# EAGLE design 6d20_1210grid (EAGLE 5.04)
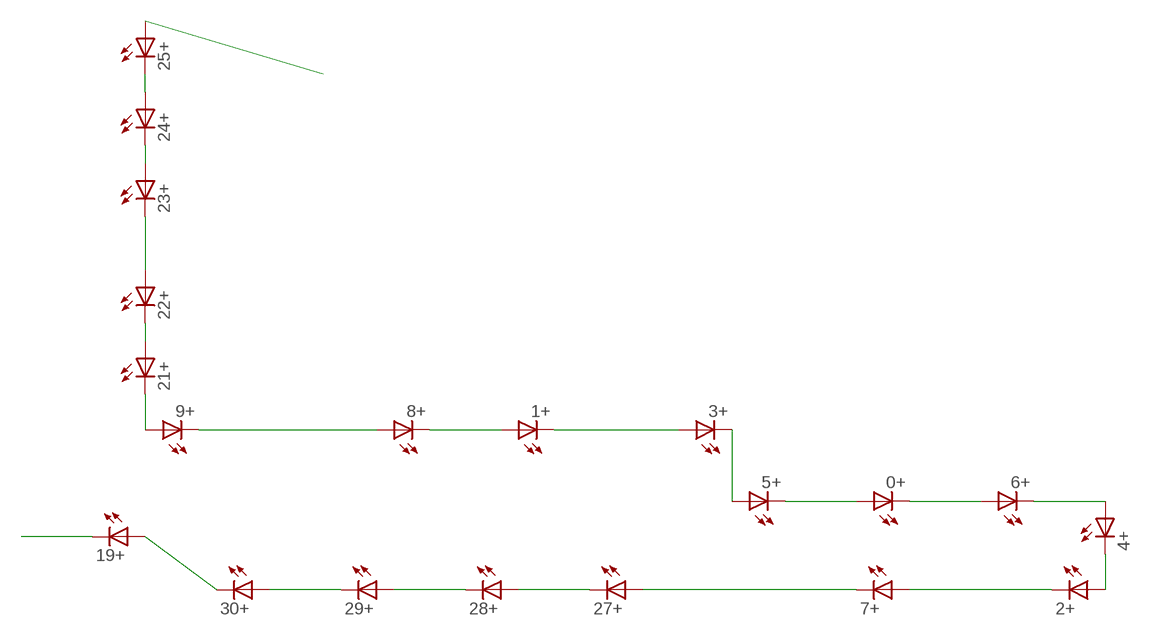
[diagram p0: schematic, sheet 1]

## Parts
0+  LED1210  [1210]
1+  LED1210  [1210]
2+  LED1210  [1210]
3+  LED1210  [1210]
4+  LED1210  [1210]
5+  LED1210  [1210]
6+  LED1210  [1210]
7+  LED1210  [1210]
8+  LED1210  [1210]
9+  LED1210  [1210]
19+  LED1210  [1210]
21+  LED1210  [1210]
22+  LED1210  [1210]
23+  LED1210  [1210]
24+  LED1210  [1210]
25+  LED1210  [1210]
27+  LED1210  [1210]
28+  LED1210  [1210]
29+  LED1210  [1210]
30+  LED1210  [1210]

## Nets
MINUS: 19+.P$2(C)
N$4: 19+.P$1(A) 30+.P$2(C)
N$6: 8+.P$1(A) 9+.P$2(C)
N$7: 29+.P$2(C) 30+.P$1(A)
N$8: 28+.P$2(C) 29+.P$1(A)
N$9: 27+.P$2(C) 28+.P$1(A)
N$12: 2+.P$2(C) 7+.P$1(A)
N$13: 7+.P$2(C) 27+.P$1(A)
N$14: 2+.P$1(A) 4+.P$2(C)
N$15: 4+.P$1(A) 6+.P$2(C)
N$16: 0+.P$2(C) 6+.P$1(A)
N$17: 0+.P$1(A) 5+.P$2(C)
N$18: 3+.P$2(C) 5+.P$1(A)
N$19: 1+.P$2(C) 3+.P$1(A)
N$20: 1+.P$1(A) 8+.P$2(C)
N$23: 9+.P$1(A) 21+.P$2(C)
N$24: 21+.P$1(A) 22+.P$2(C)
N$25: 22+.P$1(A) 23+.P$2(C)
N$26: 24+.P$1(A) 25+.P$2(C)
N$28: 23+.P$1(A) 24+.P$2(C)
PLUS: 25+.P$1(A)

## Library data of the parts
0+ 1+ 2+ 3+ 4+ 5+ 6+ 7+ 8+ 9+ 19+ 21+ 22+ 23+ 24+ 25+ 27+ 28+ 29+ 30+ = led(2):LED: LED

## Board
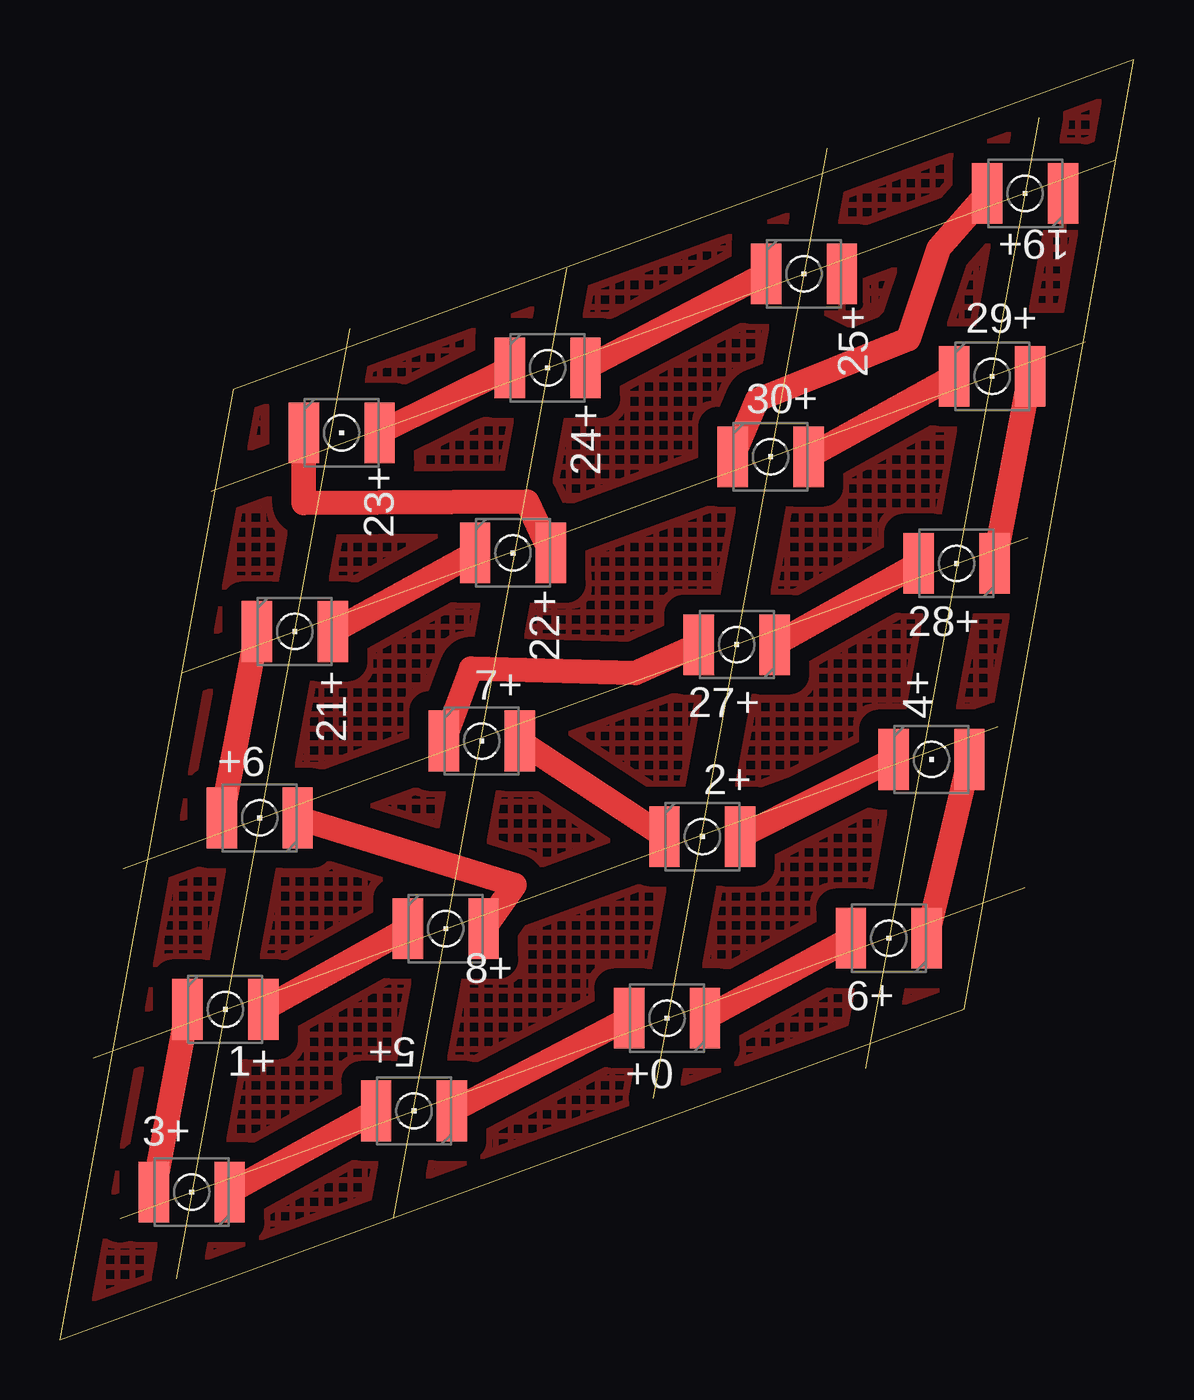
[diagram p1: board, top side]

Size 45 x 53.62 mm. Coordinates in mm from the lower left corner, seen from the top.
Outline: 21.24,44.88 13.97,5.08
Outline: 2.54,5.08 40.43,18.95
Outline: 41.02,51.18 33.75,11.38
Outline: 32.13,49.91 24.86,10.11
Outline: 12.15,42.36 4.88,2.56
Outline: 1.4,11.81 39.29,25.68
Outline: 2.67,19.74 40.56,33.61
Outline: 6.35,35.56 44.24,49.43
Outline: 5.08,27.94 42.97,41.81
Outline: 0,0 37.89,13.87 45,53.62 7.27,39.8 0,0
Copper layers (1*16): Top 0.035mm / dielectric 1.5mm / Bottom 0.035mm
Design rules "default": minimum track width 10mil, minimum drill 24mil, track to track 8mil, track to pad 8mil, pad to pad 8mil, via to via 8mil, smd to smd 8mil, copper to edge 40mil, drill to drill 8mil, minimum pad ring 10mil, minimum via ring 8mil, stop-mask expansion 4mil, vias tented up to drill 0mil, thermal gap 10mil

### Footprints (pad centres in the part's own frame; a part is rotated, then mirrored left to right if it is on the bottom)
1210 = smd 1.27 x 2.54: P$1 1.587,0; P$2 -1.587,0

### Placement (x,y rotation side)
0+  25.44,13.47 180 top
1+  6.94,13.84 0 top
2+  26.92,21.08 0 top
3+  5.53,6.19 180 top
4+  36.52,24.31 0 top
5+  14.84,9.59 180 top
6+  34.73,16.82 180 top
7+  17.68,25.08 0 top
8+  16.17,17.22 0 top
9+  8.38,21.86 180 top
19+  40.44,48.02 180 top
21+  9.85,29.67 0 top
22+  18.99,32.96 0 top
23+  11.81,37.99 0 top
24+  20.44,40.71 0 top
25+  31.18,44.65 0 top
27+  28.36,29.12 180 top
28+  37.57,32.52 180 top
29+  39.06,40.36 0 top
30+  29.78,36.99 0 top

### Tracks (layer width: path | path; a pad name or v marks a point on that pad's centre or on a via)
MINUS
  pour Top (isolate 0.813, rank 2, hatched): 44.45,53.34 38.1,43.18 43.18,43.18
N$1
  pour Top (isolate 0.813, rank 3, hatched): 6.35,39.37 0,0 38.1,13.97 44.45,53.34
N$4
  Top 1.016: 30+.P$2 29.21,39.37 35.56,41.91 36.83,45.72 19+.P$1
N$6
  Top 1.016: 8+.P$1 19.05,19.05 9+.P$2
N$7
  Top 1.016: 30+.P$1 29+.P$2
N$8
  Top 1.016: 28+.P$2 29+.P$1
N$9
  Top 1.016: 27+.P$2 28+.P$1
N$12
  Top 1.016: 7+.P$1 2+.P$2
N$13
  Top 1.016: 7+.P$2 17.24,28.12 24.13,27.94 27+.P$1
N$14
  Top 1.016: 2+.P$1 4+.P$2
N$15
  Top 1.016: 6+.P$2 4+.P$1
N$16
  Top 1.016: 0+.P$2 6+.P$1
N$17
  Top 1.016: 5+.P$2 0+.P$1
N$18
  Top 1.016: 3+.P$2 5+.P$1
N$19
  Top 1.016: 3+.P$1 1+.P$2
N$20
  Top 1.016: 1+.P$1 8+.P$2
N$23
  Top 1.016: 9+.P$1 21+.P$2
N$24
  Top 1.016: 21+.P$1 22+.P$2
N$25
  Top 1.016: 22+.P$1 19.58,35.11 10.22,35.04 23+.P$2
N$26
  Top 1.016: 24+.P$1 25+.P$2
N$28
  Top 1.016: 23+.P$1 24+.P$2
PLUS
  pour Top (isolate 0.813, hatched): 44.45,53.34 33.56,42.29 25.94,46.1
